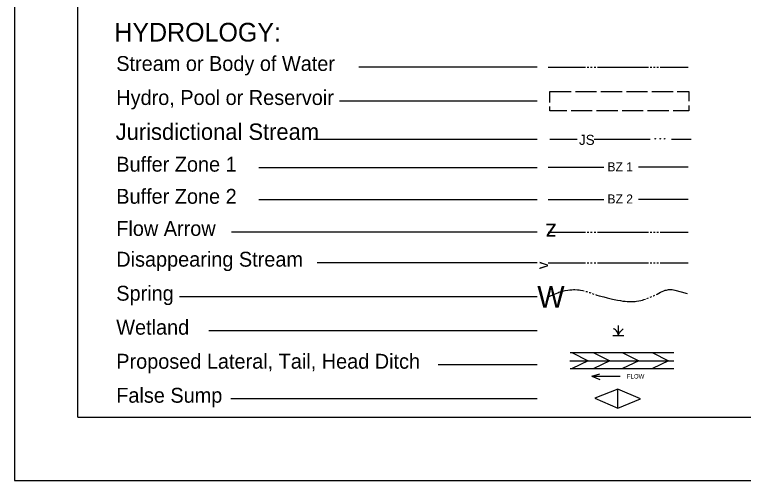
# Model space of a CAD drawing. Extents: x 2040834 to 2047174, y 618431 to 621625.
# Drawn here: x 2045074 to 2045579, y 620341 to 620664 of the extents above; entities that cross this region are included whole.
import ezdxf

# ---------------------------------------------------------------- set-up
doc = ezdxf.new("R2010")
doc.units = 0
doc.layers.add('Default', color=7, linetype='Continuous')

msp = doc.modelspace()

# ---------------------------------------------------------------- linework, layer by layer
at = {"layer": 'Default'}
for p, q in [((2045074.38, 621624.54), (2045074.38, 620341.21)), ((2045118.13, 620384.96), (2045118.13, 621580.79)), ((2045436.47, 620627.25), (2045312.87, 620627.25)), ((2045444.13, 620627.25), (2045470.06, 620627.25)), ((2045471.24, 620627.25), (2045472.41, 620627.25)), ((2045473.59, 620627.25), (2045474.77, 620627.25)), ((2045475.95, 620627.25), (2045477.12, 620627.25)), ((2045478.3, 620627.25), (2045513.61, 620627.25)), ((2045514.79, 620627.25), (2045515.97, 620627.25)), ((2045517.14, 620627.25), (2045518.32, 620627.25)), ((2045519.5, 620627.25), (2045520.67, 620627.25)), ((2045521.85, 620627.25), (2045541.24, 620627.25)), ((2045445.38, 620610.27), (2045460.1, 620610.27)), ((2045445.38, 620602.85), (2045445.38, 620610.27)), ((2045463.04, 620610.27), (2045477.75, 620610.27)), ((2045480.7, 620610.27), (2045495.41, 620610.27)), ((2045498.35, 620610.27), (2045513.07, 620610.27)), ((2045516.01, 620610.27), (2045530.72, 620610.27)), ((2045436.47, 620603.7), (2045299.47, 620603.7)), ((2045474.78, 620596.94), (2045460.07, 620596.94)), ((2045492.44, 620596.94), (2045477.73, 620596.94)), ((2045510.1, 620596.94), (2045495.38, 620596.94)), ((2045527.75, 620596.94), (2045513.04, 620596.94)), ((2045436.47, 620577.11), (2045281.56, 620577.11)), ((2045436.47, 620557.55), (2045243.72, 620557.55)), ((2045444.13, 620558.06), (2045482.74, 620558.06)), ((2045541.24, 620558.06), (2045506.75, 620558.06)), ((2045436.47, 620535.34), (2045243.72, 620535.34)), ((2045444.13, 620535.72), (2045482.74, 620535.72)), ((2045541.24, 620535.72), (2045506.75, 620535.72)), ((2045436.47, 620513.12), (2045224.78, 620513.12)), ((2045444.13, 620513.12), (2045470.06, 620513.12)), ((2045471.24, 620513.12), (2045472.41, 620513.12)), ((2045473.59, 620513.12), (2045474.77, 620513.12)), ((2045475.95, 620513.12), (2045477.12, 620513.12)), ((2045478.3, 620513.12), (2045513.61, 620513.12)), ((2045514.79, 620513.12), (2045515.97, 620513.12)), ((2045517.14, 620513.12), (2045518.32, 620513.12)), ((2045519.5, 620513.12), (2045520.67, 620513.12)), ((2045521.85, 620513.12), (2045541.24, 620513.12)), ((2045436.47, 620491.8), (2045284.02, 620491.8)), ((2045444.13, 620491.8), (2045470.06, 620491.8)), ((2045471.24, 620491.8), (2045472.41, 620491.8)), ((2045473.59, 620491.8), (2045474.77, 620491.8)), ((2045475.95, 620491.8), (2045477.12, 620491.8)), ((2045478.3, 620491.8), (2045513.61, 620491.8)), ((2045514.79, 620491.8), (2045515.97, 620491.8)), ((2045517.14, 620491.8), (2045518.32, 620491.8)), ((2045519.5, 620491.8), (2045520.67, 620491.8)), ((2045521.85, 620491.8), (2045541.24, 620491.8)), ((2045436.47, 620468.26), (2045188.72, 620468.26)), ((2045474.75, 620470.55), (2045475.87, 620470.17)), ((2045512.66, 620467.11), (2045513.74, 620467.55)), ((2045514.85, 620467.98), (2045515.92, 620468.43)), ((2045492.82, 620441.52), (2045492.82, 620448.44)), ((2045436.47, 620444.71), (2045209.04, 620444.71)), ((2045489.1, 620441.52), (2045496.6, 620441.52)), ((2045459.41, 620429.71), (2045531.22, 620429.71)), ((2045460.47, 620429.71), (2045471.99, 620424.06)), ((2045475.43, 620429.71), (2045486.95, 620424.06)), ((2045495.38, 620429.71), (2045506.95, 620424.06)), ((2045516.26, 620429.71), (2045527.56, 620424.06)), ((2045436.47, 620421.17), (2045367.99, 620421.17)), ((2045459.1, 620424.06), (2045531.22, 620424.06)), ((2045471.99, 620424.06), (2045460.79, 620418.58)), ((2045486.95, 620424.06), (2045475.8, 620418.58)), ((2045506.95, 620424.06), (2045495.79, 620418.58)), ((2045527.56, 620424.06), (2045516.57, 620418.58)), ((2045459.41, 620418.58), (2045531.22, 620418.58)), ((2045474.41, 620413.28), (2045480.06, 620414.87)), ((2045474.41, 620413.28), (2045494.01, 620413.28)), ((2045474.41, 620413.28), (2045480.06, 620410.99)), ((2045492.44, 620404.24), (2045476.46, 620398.03)), ((2045492.44, 620391.23), (2045492.44, 620404.24)), ((2045508.11, 620397.73), (2045492.44, 620404.24)), ((2045436.47, 620397.63), (2045224.27, 620397.63)), ((2045476.46, 620398.03), (2045492.44, 620391.23)), ((2045492.44, 620391.23), (2045508.11, 620397.73)), ((2045118.13, 620384.96), (2047013.93, 620384.96)), ((2045074.38, 620341.21), (2047057.71, 620341.21))]:
    msp.add_line(p, q, dxfattribs=at)
for points in [[(2045533.67, 620610.27), (2045541.7, 620610.27), (2045541.7, 620603.59)], [(2045457.13, 620596.94), (2045445.38, 620596.94), (2045445.38, 620599.91)], [(2045541.7, 620600.64), (2045541.7, 620596.94), (2045530.69, 620596.94)], [(2045445.38, 620577.34), (2045464.22, 620577.34)], [(2045476.04, 620577.34), (2045492.55, 620577.34)], [(2045492.55, 620577.34), (2045514.91, 620577.34)], [(2045529.74, 620577.34), (2045543.18, 620577.34)], [(2045444.15, 620468.26), (2045447.49, 620469.65), (2045450.84, 620471.07), (2045451.68, 620471.39), (2045453.17, 620471.9), (2045454.32, 620472.21), (2045456.04, 620472.61), (2045457.77, 620472.92), (2045459.23, 620473.1), (2045460.53, 620473.2), (2045461.66, 620473.23), (2045462.66, 620473.23), (2045464.41, 620473.13), (2045465.72, 620472.99), (2045466.69, 620472.85), (2045468.15, 620472.57), (2045469.15, 620472.33)], [(2045470.3, 620472.02), (2045470.84, 620471.86), (2045471.41, 620471.68)], [(2045472.53, 620471.32), (2045473.02, 620471.15), (2045473.65, 620470.93)], [(2045519.14, 620469.9), (2045519.7, 620470.18), (2045522.01, 620471.39), (2045523.19, 620471.96), (2045524.41, 620472.46), (2045525.34, 620472.77), (2045526.16, 620472.98), (2045526.9, 620473.13), (2045527.55, 620473.23), (2045528.69, 620473.3), (2045529.55, 620473.3), (2045530.18, 620473.26), (2045531.12, 620473.13), (2045532.05, 620472.92), (2045536.23, 620471.77), (2045540.39, 620470.61)], [(2045476.99, 620469.79), (2045477.89, 620469.48), (2045479.54, 620468.99), (2045482.7, 620468.15), (2045485.08, 620467.55), (2045488.66, 620466.72), (2045492.26, 620465.97), (2045494.26, 620465.62), (2045496.03, 620465.36), (2045497.59, 620465.18), (2045498.96, 620465.06), (2045500.15, 620465), (2045501.21, 620464.97), (2045503.03, 620465), (2045504.4, 620465.09), (2045505.43, 620465.21), (2045506.95, 620465.43), (2045508.45, 620465.75), (2045509.58, 620466.06), (2045510.57, 620466.36), (2045511.55, 620466.71)], [(2045517.01, 620468.89), (2045517.25, 620468.99), (2045518.09, 620469.37)], [(2045492.82, 620441.52), (2045492.65, 620442.35), (2045492.41, 620443.18), (2045492, 620443.95), (2045491.46, 620444.65), (2045490.87, 620445.31), (2045490.16, 620445.78), (2045489.4, 620446.19)], [(2045492.82, 620441.52), (2045493.18, 620442.41), (2045493.59, 620443.3), (2045494.12, 620444.12), (2045494.77, 620444.83), (2045495.48, 620445.48), (2045496.25, 620446.07)]]:
    msp.add_lwpolyline(points, dxfattribs=at)
for centre in [(2045518.37, 620577.67), (2045521.85, 620577.67), (2045524.9, 620577.67)]:
    msp.add_ellipse(centre, major_axis=(0, 0.232), ratio=0.938496, dxfattribs=at)

# ---------------------------------------------------------------- texts
for s, height, p in [('HYDROLOGY:', 12.948, (2045143.52, 620644.93)), ('Stream or Body of Water', 10.2996, (2045144.86, 620624.58)), ('Hydro, Pool or Reservoir', 10.2996, (2045144.86, 620601.04)), ('Jurisdictional Stream', 11.3543, (2045144.46, 620576.87)), ('JS', 6.951, (2045465.54, 620573.43)), ('Buffer Zone 1', 10.2996, (2045144.86, 620554.88)), ('BZ 1', 6.256, (2045485.27, 620555.1)), ('Buffer Zone 2', 10.2996, (2045144.86, 620532.67)), ('BZ 2', 6.256, (2045485.27, 620532.86)), ('Flow Arrow', 10.3, (2045144.86, 620510.46)), ('Disappearing Stream', 10.2996, (2045144.86, 620489.13)), ('Spring', 10.3, (2045144.86, 620465.59)), ('W', 15.01, (2045436.64, 620460.75)), ('Wetland', 10.3, (2045144.86, 620442.05)), ('Proposed Lateral, Tail, Head Ditch', 10.2996, (2045144.86, 620418.51)), ('FLOW', 3.052, (2045498.65, 620411.7)), ('False Sump', 10.3, (2045144.86, 620394.97))]:
    msp.add_text(s, height=height, dxfattribs=at).set_placement(p)
for s, height, rotation, p in [('z', 11.77, 180, (2045450.03, 620519.01)), ('v', 7.77, 89.7591, (2045444.13, 620487.4))]:
    msp.add_text(s, height=height, rotation=rotation, dxfattribs=at).set_placement(p)

doc.saveas('drawing.dxf')
